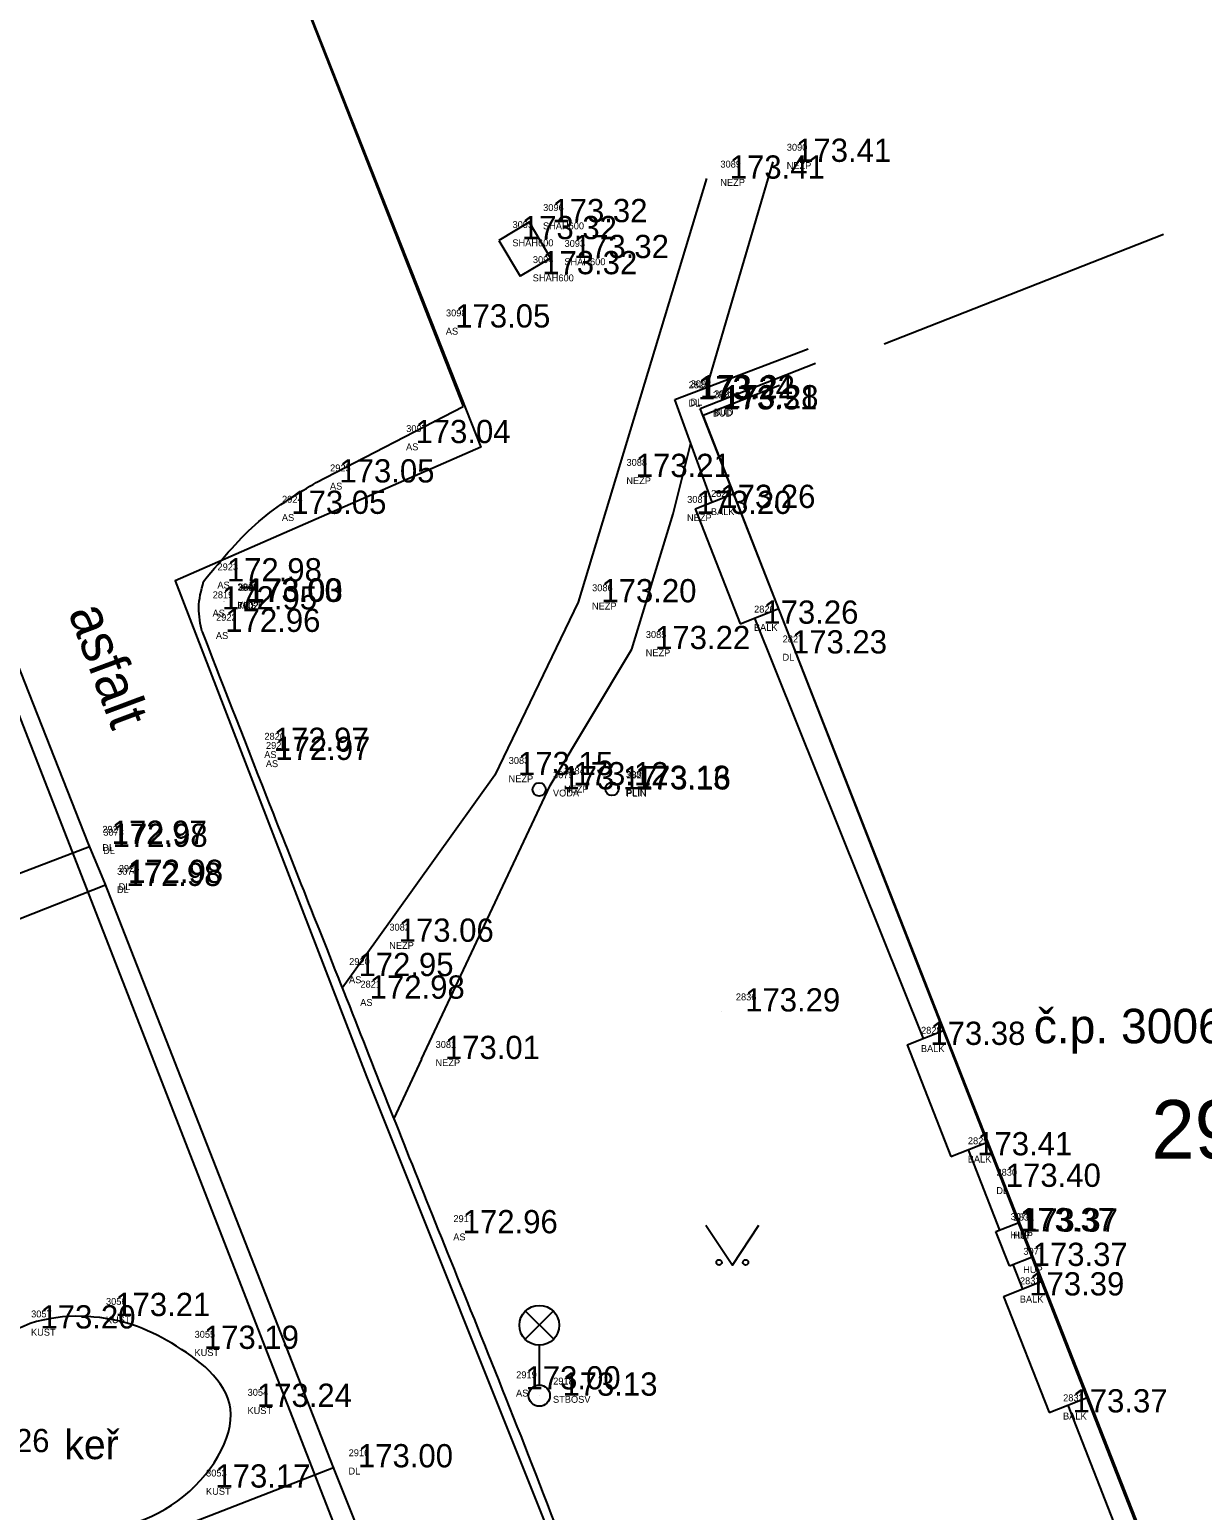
# Model space of a CAD drawing. Extents: x -566117 to -565580, y -1202428 to -1201938.
# Drawn here: x -565664.29 to -565642.22, y -1202039.2 to -1202011.32 of the extents above; entities that cross this region are included whole.
import ezdxf

# ---------------------------------------------------------------- set-up
doc = ezdxf.new("R2010")
doc.units = 0
for name, color, linetype in [('Bod', 7, 'Continuous'), ('BUDOVY_MĚŘ (Construction)', 7, 'Continuous'), ('CIZÍ_NADZEM', 7, 'Continuous'), ('Implicitní', 7, 'Continuous'), ('Katastr', 7, 'Continuous'), ('Kod', 7, 'Continuous'), ('Plin', 7, 'Continuous'), ('POMOC_POPIS', 7, 'Continuous'), ('Voda', 7, 'Continuous'), ('Výška', 7, 'Continuous'), ('ZELEŇ', 7, 'Continuous'), ('ZN_KULTUR', 7, 'Continuous'), ('Zpevněné plohy', 7, 'Continuous'), ('Číslo', 7, 'Continuous'), ('Číslo popisné', 7, 'Continuous')]:
    doc.layers.add(name, color=color, linetype=linetype)

# ---------------------------------------------------------------- blocks, each defined once
blk = doc.blocks.new('A$C69D74C1E')
at = {"layer": 'Katastr'}
blk.add_line((406.98, 37.41), (417.53, 11.04), dxfattribs=at)
for points in [[(385.19, 114.21), (383.36, 113.36), (381.71, 112.17), (381.1, 111.33), (380.71, 110.4), (380.47, 108.89), (380.54, 106.39), (380.78, 104.37), (381.07, 103.42), (393.45, 72.27), (399.32, 74.11), (409.13, 49.26), (403.38, 46.74), (406.98, 37.41)], [(446.91, -78.1), (443.73, -70.06), (442.96, -69.37), (431.86, -40.35), (433.02, -38.37), (428.19, -26.51), (420.97, -8.39), (414.6, 8.02), (406.54, 28.55), (397.51, 51.73), (392.1, 64.9), (383.47, 87.48), (375.32, 106.51), (374.71, 107), (373.34, 107.64), (371.88, 108.02), (370.59, 108.16), (369.35, 107.99)], [(416.723, 51.2), (421.98, 53.27)], [(426.586, 20.44), (425.05, 19.84), (419.18, 34.85), (413.32, 49.86), (414.756, 50.425)]]:
    blk.add_lwpolyline(points, dxfattribs=at)
blk.add_text('2928', height=1.1, dxfattribs=at).set_placement((421.753, 35.867))
blk = doc.blocks.new('6.560')
at = {"layer": 'CIZÍ_NADZEM'}
for p, q in [((-0.528, 2.124), (0.528, 3.18)), ((0.544, 2.13), (-0.512, 3.188)), ((0, 1.9), (0, 0.4))]:
    blk.add_line(p, q, dxfattribs=at)
for centre, radius in [((0, 2.65), 0.75), ((0, 0), 0.4)]:
    blk.add_circle(centre, radius, dxfattribs=at)
blk = doc.blocks.new('POINT_DISPLAY')
at = {"layer": 'Implicitní'}
blk.add_line((0, 0), (0, 0), dxfattribs=at)
blk = doc.blocks.new('3.140_2')
at = {"layer": 'ZN_KULTUR'}
blk.add_lwpolyline([(-1, 1.5), (0, 0), (1, 1.5)], dxfattribs=at)
for centre in [(-0.5, 0.1), (0.5, 0.1)]:
    blk.add_circle(centre, 0.1, dxfattribs=at)

msp = doc.modelspace()

# ---------------------------------------------------------------- linework, layer by layer
at = {"layer": 'BUDOVY_MĚŘ (Construction)'}
for p, q in [((-565651.669, -1202018.452), (-565649.501, -1202017.601)), ((-565639.785, -1202048.724), (-565651.669, -1202018.452)), ((-565651.766, -1202020.343), (-565651.038, -1202020.057)), ((-565651.766, -1202020.343), (-565650.917, -1202022.506)), ((-565650.917, -1202022.506), (-565650.189, -1202022.22)), ((-565647.773, -1202030.434), (-565647.073, -1202030.159)), ((-565647.773, -1202030.434), (-565646.948, -1202032.536)), ((-565646.948, -1202032.536), (-565646.248, -1202032.261)), ((-565645.956, -1202035.167), (-565645.22, -1202034.878)), ((-565645.956, -1202035.167), (-565645.098, -1202037.352)), ((-565645.098, -1202037.352), (-565644.363, -1202037.063))]:
    msp.add_line(p, q, dxfattribs=at)
at = {"layer": 'Implicitní'}
for p, q in [((-565650.3, -1202013.812), (-565651.552, -1202018.057)), ((-565651.55, -1202014.128), (-565653.965, -1202022.103)), ((-565654.888, -1202014.947), (-565655.461, -1202015.289)), ((-565654.888, -1202014.947), (-565654.485, -1202015.623)), ((-565655.461, -1202015.289), (-565655.058, -1202015.965)), ((-565654.485, -1202015.623), (-565655.058, -1202015.965)), ((-565652.176, -1202020.44), (-565651.847, -1202019.104)), ((-565652.955, -1202022.984), (-565652.176, -1202020.44)), ((-565653.965, -1202022.103), (-565655.535, -1202025.355)), ((-565654.492, -1202025.548), (-565652.955, -1202022.984)), ((-565655.535, -1202025.355), (-565657.781, -1202028.493)), ((-565656.912, -1202030.7), (-565654.492, -1202025.548)), ((-565657.781, -1202028.493), (-565658.406, -1202029.366)), ((-565656.912, -1202030.7), (-565657.437, -1202031.82)), ((-565646.625, -1202032.409), (-565646.625, -1202032.409)), ((-565646.102, -1202033.948), (-565645.654, -1202033.772)), ((-565645.848, -1202034.595), (-565646.102, -1202033.948)), ((-565645.848, -1202034.595), (-565645.4, -1202034.419))]:
    msp.add_line(p, q, dxfattribs=at)
at = {"layer": 'Plin'}
msp.add_circle((-565653.329, -1202025.615), 0.125, dxfattribs=at)
at = {"layer": 'Voda'}
msp.add_circle((-565654.7, -1202025.624), 0.125, dxfattribs=at)
at = {"layer": 'ZELEŇ'}
msp.add_open_spline([(-565664.021, -1202039.781), (-565663.033, -1202039.632), (-565661.475, -1202039.398), (-565659.999, -1202037.235), (-565661.553, -1202035.997), (-565662.941, -1202035.416), (-565665.167, -1202035.677), (-565665.941, -1202038.261), (-565667.913, -1202040.139), (-565670.275, -1202041.079), (-565671.815, -1202041.457), (-565672.553, -1202041.639)], degree=3, dxfattribs=at)
at = {"layer": 'Zpevněné plohy'}
for p, q in [((-565665.237, -1201995.209), (-565656.132, -1202018.417)), ((-565652.148, -1202018.283), (-565649.638, -1202017.332)), ((-565658.897, -1202019.847), (-565656.132, -1202018.417)), ((-565651.44, -1202020.215), (-565652.148, -1202018.283)), ((-565647.467, -1202030.314), (-565650.641, -1202022.398)), ((-565663.167, -1202026.706), (-565671.29, -1202029.807)), ((-565670.918, -1202030.574), (-565662.863, -1202027.42)), ((-565646.625, -1202032.409), (-565646.035, -1202033.922)), ((-565645.782, -1202034.569), (-565645.603, -1202035.029)), ((-565644.749, -1202037.214), (-565643.517, -1202040.368)), ((-565663.639, -1202040.353), (-565658.569, -1202038.386))]:
    msp.add_line(p, q, dxfattribs=at)
msp.add_lwpolyline([(-565636.32, -1202094.922), (-565642.594, -1202078.899), (-565643.478, -1202076.72), (-565644.098, -1202075.295), (-565646.528, -1202069.052), (-565649.997, -1202060.239), (-565652.029, -1202054.989), (-565653.778, -1202050.441), (-565655.131, -1202047.048), (-565657.97, -1202039.895), (-565658.569, -1202038.386), (-565662.876, -1202027.386), (-565663.184, -1202026.65), (-565666.528, -1202018.175)], dxfattribs=at)
for points in [[(-565661.017, -1202021.709), (-565660.638, -1202021.253), (-565660.028, -1202020.518), (-565659.209, -1202020.032), (-565658.897, -1202019.847)], [(-565661.044, -1202022.66), (-565661.075, -1202022.519), (-565661.145, -1202022.201), (-565661.063, -1202021.885), (-565661.017, -1202021.709)], [(-565661.044, -1202022.66), (-565660.731, -1202023.463), (-565659.835, -1202025.769), (-565658.922, -1202028.067), (-565658.327, -1202029.564)], [(-565658.327, -1202029.564), (-565657.747, -1202031.038), (-565656.78, -1202033.493), (-565654.587, -1202038.874), (-565652.173, -1202045.449), (-565649.971, -1202050.973), (-565648.944, -1202053.552)]]:
    msp.add_open_spline(points, degree=3, dxfattribs=at)

# ---------------------------------------------------------------- block references
at = {"layer": 'Bod'}
for p in [(-565650.3, -1202013.812), (-565651.55, -1202014.128), (-565654.888, -1202014.947), (-565655.464, -1202015.267), (-565654.485, -1202015.623), (-565655.081, -1202015.927), (-565656.716, -1202016.93), (-565652.148, -1202018.283), (-565652.111, -1202018.263), (-565651.691, -1202018.472), (-565651.669, -1202018.452), (-565657.465, -1202019.106), (-565653.319, -1202019.744), (-565658.897, -1202019.847), (-565651.727, -1202020.327), (-565659.802, -1202020.438), (-565652.176, -1202020.44), (-565661.017, -1202021.709), (-565661.107, -1202022.237), (-565660.641, -1202022.088), (-565660.635, -1202022.095), (-565660.635, -1202022.095), (-565660.629, -1202022.094), (-565660.626, -1202022.094), (-565653.965, -1202022.103), (-565650.917, -1202022.506), (-565661.044, -1202022.66), (-565652.955, -1202022.984), (-565650.379, -1202023.066), (-565660.134, -1202024.9), (-565660.104, -1202025.07), (-565655.535, -1202025.355), (-565654.7, -1202025.624), (-565654.492, -1202025.548), (-565653.329, -1202025.615), (-565653.32, -1202025.627), (-565663.184, -1202026.65), (-565663.167, -1202026.706), (-565662.908, -1202027.442), (-565662.876, -1202027.386), (-565657.781, -1202028.493), (-565658.539, -1202029.138), (-565658.327, -1202029.564), (-565651.259, -1202029.805), (-565647.773, -1202030.434), (-565656.912, -1202030.7), (-565646.892, -1202032.513), (-565646.353, -1202033.106), (-565656.576, -1202033.98), (-565646.087, -1202033.942), (-565646.032, -1202033.95), (-565645.848, -1202034.595), (-565645.912, -1202035.15), (-565663.117, -1202035.538), (-565661.448, -1202036.156), (-565655.394, -1202036.919), (-565654.698, -1202037.037), (-565660.45, -1202037.248), (-565645.098, -1202037.352), (-565658.549, -1202038.386), (-565661.231, -1202038.767)]:
    msp.add_blockref('POINT_DISPLAY', p, dxfattribs=at)
at = {"layer": 'CIZÍ_NADZEM', "xscale": 0.5, "yscale": 0.5}
msp.add_blockref('6.560', (-565654.698, -1202037.037), dxfattribs=at)
at = {"layer": 'Implicitní'}
msp.add_blockref('A$C69D74C1E', (-566064.93, -1202068.44), dxfattribs=at)
at = {"layer": 'ZN_KULTUR', "xscale": 0.5, "yscale": 0.5}
msp.add_blockref('3.140_2', (-565651.063, -1202034.577), dxfattribs=at)

# ---------------------------------------------------------------- texts
at = {"layer": 'Kod'}
for s, p in [('NEZP', (-565650.04, -1202013.946)), ('NEZP', (-565651.29, -1202014.263)), ('SHAH600', (-565654.628, -1202015.081)), ('SHAH600', (-565655.204, -1202015.401)), ('SHAH600', (-565654.225, -1202015.757)), ('SHAH600', (-565654.821, -1202016.061)), ('AS', (-565656.457, -1202017.065)), ('DL', (-565651.888, -1202018.417)), ('DL', (-565651.852, -1202018.398)), ('BUD', (-565651.432, -1202018.606)), ('BUD', (-565651.409, -1202018.586)), ('AS', (-565657.206, -1202019.241)), ('NEZP', (-565653.059, -1202019.878)), ('AS', (-565658.638, -1202019.981)), ('BALK', (-565651.467, -1202020.462)), ('AS', (-565659.543, -1202020.572)), ('NEZP', (-565651.917, -1202020.575)), ('AS', (-565660.757, -1202021.843)), ('AS', (-565660.848, -1202022.371)), ('KUST', (-565660.382, -1202022.222)), ('7002', (-565660.376, -1202022.23)), ('7002', (-565660.376, -1202022.23)), ('7002', (-565660.366, -1202022.229)), ('NEZP', (-565653.706, -1202022.238)), ('BALK', (-565650.657, -1202022.64)), ('AS', (-565660.785, -1202022.794)), ('NEZP', (-565652.695, -1202023.118)), ('DL', (-565650.119, -1202023.201)), ('AS', (-565659.875, -1202025.034)), ('AS', (-565659.845, -1202025.205)), ('NEZP', (-565655.276, -1202025.489)), ('VODA', (-565654.441, -1202025.758)), ('NEZP', (-565654.233, -1202025.683)), ('PLIN', (-565653.07, -1202025.749)), ('PLIN', (-565653.061, -1202025.762)), ('DL', (-565662.925, -1202026.785)), ('DL', (-565662.908, -1202026.84)), ('DL', (-565662.648, -1202027.576)), ('DL', (-565662.616, -1202027.521)), ('NEZP', (-565657.522, -1202028.627)), ('AS', (-565658.279, -1202029.273)), ('AS', (-565658.068, -1202029.699)), ('BALK', (-565647.514, -1202030.568)), ('NEZP', (-565656.652, -1202030.834)), ('BALK', (-565646.632, -1202032.648)), ('DL', (-565646.094, -1202033.241)), ('AS', (-565656.317, -1202034.114)), ('HUP', (-565645.827, -1202034.076)), ('HUP', (-565645.773, -1202034.084)), ('HUP', (-565645.588, -1202034.729)), ('BALK', (-565645.652, -1202035.284)), ('KUST', (-565662.857, -1202035.672)), ('KUST', (-565664.266, -1202035.907)), ('KUST', (-565661.189, -1202036.29)), ('AS', (-565655.135, -1202037.053)), ('STBOSV', (-565654.439, -1202037.171)), ('KUST', (-565660.191, -1202037.383)), ('BALK', (-565644.838, -1202037.486)), ('DL', (-565658.289, -1202038.521)), ('KUST', (-565660.972, -1202038.902))]:
    msp.add_text(s, height=0.13, dxfattribs=at).set_placement(p)
at = {"layer": 'POMOC_POPIS'}
msp.add_text('asfalt', height=0.75, rotation=290.4548, dxfattribs=at).set_placement((-565663.57, -1202022.289))
at = {"layer": 'Výška'}
for s, p in [('173.41', (-565649.862, -1202013.812)), ('173.41', (-565651.112, -1202014.128)), ('173.32', (-565654.45, -1202014.947)), ('173.32', (-565655.026, -1202015.267)), ('173.32', (-565654.047, -1202015.623)), ('173.32', (-565654.643, -1202015.927)), ('173.05', (-565656.279, -1202016.93)), ('173.24', (-565651.71, -1202018.283)), ('173.22', (-565651.674, -1202018.263)), ('173.31', (-565651.253, -1202018.472)), ('173.28', (-565651.231, -1202018.452)), ('173.04', (-565657.028, -1202019.106)), ('173.05', (-565658.46, -1202019.847)), ('173.21', (-565652.881, -1202019.744)), ('173.05', (-565659.365, -1202020.438)), ('173.20', (-565651.739, -1202020.44)), ('173.26', (-565651.289, -1202020.327)), ('172.98', (-565660.579, -1202021.709)), ('173.00', (-565660.204, -1202022.088)), ('173.03', (-565660.198, -1202022.095)), ('173.00', (-565660.198, -1202022.095)), ('173.00', (-565660.192, -1202022.094)), ('173.03', (-565660.188, -1202022.094)), ('173.20', (-565653.528, -1202022.103)), ('172.95', (-565660.67, -1202022.237)), ('172.96', (-565660.607, -1202022.66)), ('173.26', (-565650.479, -1202022.506)), ('173.22', (-565652.517, -1202022.984)), ('173.23', (-565649.941, -1202023.066)), ('172.97', (-565659.697, -1202024.9)), ('172.97', (-565659.667, -1202025.07)), ('173.15', (-565655.098, -1202025.355)), ('173.12', (-565654.055, -1202025.548)), ('173.17', (-565654.263, -1202025.624)), ('173.13', (-565652.892, -1202025.615)), ('173.16', (-565652.882, -1202025.627)), ('172.97', (-565662.747, -1202026.65)), ('172.98', (-565662.73, -1202026.706)), ('172.98', (-565662.47, -1202027.442)), ('172.98', (-565662.438, -1202027.386)), ('173.06', (-565657.344, -1202028.493)), ('172.95', (-565658.101, -1202029.138)), ('172.98', (-565657.89, -1202029.564)), ('173.29', (-565650.822, -1202029.805)), ('173.38', (-565647.336, -1202030.434)), ('173.01', (-565656.474, -1202030.7)), ('173.41', (-565646.454, -1202032.513)), ('173.40', (-565645.916, -1202033.106)), ('172.96', (-565656.139, -1202033.98)), ('173.37', (-565645.649, -1202033.942)), ('173.37', (-565645.595, -1202033.95)), ('173.37', (-565645.41, -1202034.595)), ('173.39', (-565645.474, -1202035.15)), ('173.21', (-565662.679, -1202035.538)), ('173.20', (-565664.088, -1202035.772)), ('173.19', (-565661.011, -1202036.156)), ('173.00', (-565654.957, -1202036.919)), ('173.24', (-565660.013, -1202037.248)), ('173.13', (-565654.261, -1202037.037)), ('173.37', (-565644.66, -1202037.352)), ('173.26', (-565665.707, -1202038.1)), ('173.00', (-565658.111, -1202038.386)), ('173.17', (-565660.794, -1202038.767))]:
    msp.add_text(s, height=0.4375, dxfattribs=at).set_placement(p)
at = {"layer": 'ZELEŇ'}
msp.add_text('keř', height=0.55, dxfattribs=at).set_placement((-565663.637, -1202038.232))
at = {"layer": 'Číslo'}
for s, p in [('3090', (-565650.038, -1202013.602)), ('3089', (-565651.288, -1202013.919)), ('3096', (-565654.625, -1202014.737)), ('3095', (-565655.201, -1202015.057)), ('3093', (-565654.222, -1202015.413)), ('3094', (-565654.818, -1202015.717)), ('3098', (-565656.454, -1202016.721)), ('2824', (-565651.885, -1202018.073)), ('3092', (-565651.849, -1202018.054)), ('2823', (-565651.429, -1202018.262)), ('3091', (-565651.406, -1202018.242)), ('3097', (-565657.203, -1202018.897)), ('2925', (-565658.635, -1202019.638)), ('3088', (-565653.056, -1202019.534)), ('2924', (-565659.54, -1202020.228)), ('3087', (-565651.914, -1202020.231)), ('2825', (-565651.464, -1202020.118)), ('2923', (-565660.754, -1202021.5)), ('3242', (-565660.379, -1202021.879)), ('3290', (-565660.373, -1202021.886)), ('2817', (-565660.373, -1202021.886)), ('7002', (-565660.367, -1202021.884)), ('2818', (-565660.363, -1202021.885)), ('3086', (-565653.703, -1202021.894)), ('2819', (-565660.845, -1202022.027)), ('2922', (-565660.782, -1202022.45)), ('2826', (-565650.654, -1202022.296)), ('3085', (-565652.692, -1202022.774)), ('2827', (-565650.116, -1202022.857)), ('2820', (-565659.872, -1202024.69)), ('2921', (-565659.842, -1202024.861)), ('3083', (-565655.273, -1202025.145)), ('3079', (-565654.438, -1202025.414)), ('3084', (-565654.23, -1202025.339)), ('3080', (-565653.067, -1202025.405)), ('2822', (-565653.058, -1202025.418)), ('2927', (-565662.922, -1202026.441)), ('3073', (-565662.905, -1202026.496)), ('2926', (-565662.613, -1202027.177)), ('3074', (-565662.645, -1202027.232)), ('3082', (-565657.519, -1202028.283)), ('2920', (-565658.276, -1202028.929)), ('2821', (-565658.065, -1202029.355)), ('2836', (-565650.997, -1202029.596)), ('2828', (-565647.511, -1202030.224)), ('3081', (-565656.649, -1202030.49)), ('2829', (-565646.629, -1202032.304)), ('2830', (-565646.091, -1202032.897)), ('2917', (-565656.314, -1202033.77)), ('3078', (-565645.824, -1202033.732)), ('2831', (-565645.77, -1202033.74)), ('3077', (-565645.585, -1202034.385)), ('2832', (-565645.649, -1202034.94)), ('3057', (-565664.263, -1202035.563)), ('3056', (-565662.854, -1202035.328)), ('3055', (-565661.186, -1202035.947)), ('2919', (-565655.132, -1202036.709)), ('2918', (-565654.436, -1202036.827)), ('3054', (-565660.188, -1202037.039)), ('2833', (-565644.836, -1202037.142)), ('2916', (-565658.286, -1202038.177)), ('3053', (-565660.969, -1202038.558))]:
    msp.add_text(s, height=0.13, dxfattribs=at).set_placement(p)
at = {"layer": 'Číslo popisné'}
msp.add_text('č.p. 3006, 3005', height=0.65, dxfattribs=at).set_placement((-565645.389, -1202030.404))

doc.saveas('drawing.dxf')
